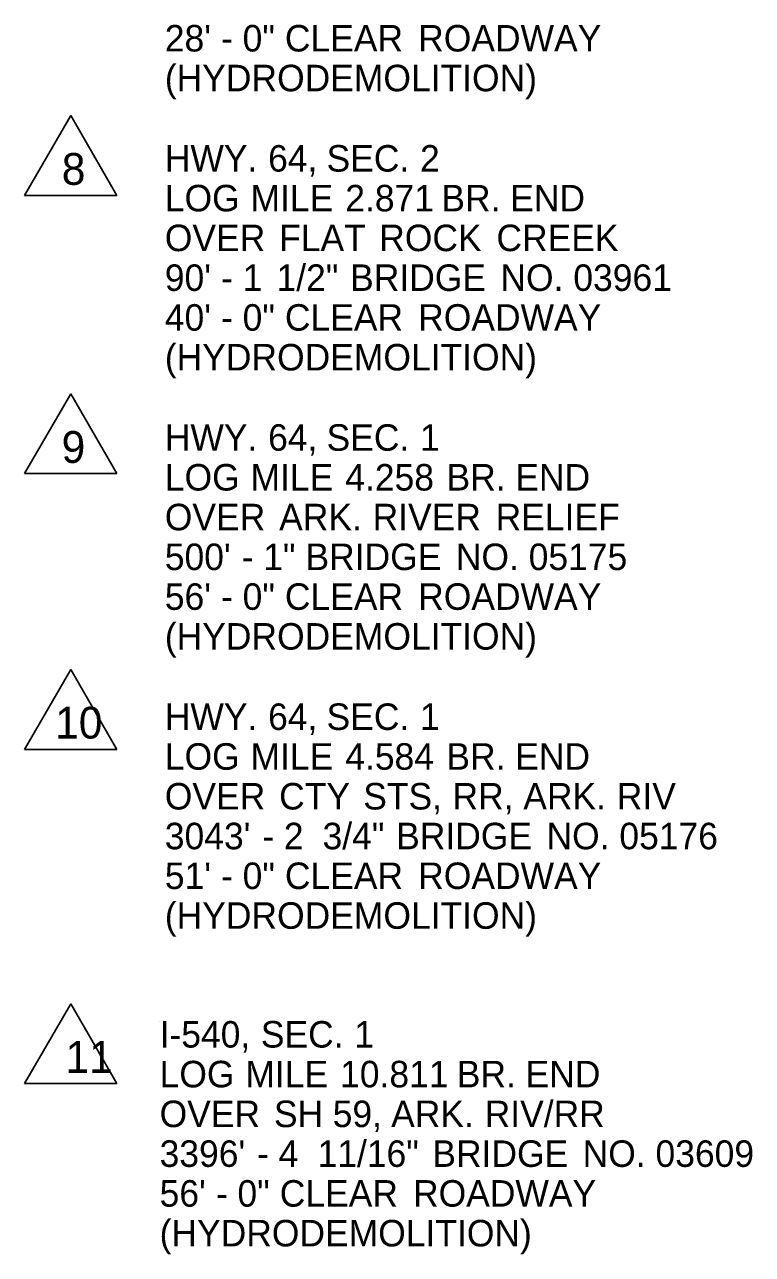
# Model space of a CAD drawing. Extents: x -17668 to 16999, y -17303 to 5867.
# Drawn here: x 1935 to 3994, y -2270 to 1209 of the extents above; entities that cross this region are included whole.
import ezdxf

# ---------------------------------------------------------------- set-up
doc = ezdxf.new("R2010")
doc.units = 0
doc.layers.add('48', color=7, linetype='Continuous')
doc.layers.add('Default', color=7, linetype='Continuous')

msp = doc.modelspace()

# ---------------------------------------------------------------- linework, layer by layer
at = {"layer": '48'}
for p, q in [((2065.7, 951.7), (1935.1, 725.5)), ((2196.3, 725.5), (2065.7, 951.7)), ((1935.1, 725.5), (2196.3, 725.5)), ((2065.7, 165.1), (1935.1, -61.1)), ((2196.3, -61.1), (2065.7, 165.1)), ((1935.1, -61.1), (2196.3, -61.1)), ((2065.7, -614.8), (1935.1, -841)), ((2196.3, -841), (2065.7, -614.8)), ((1935.1, -841), (2196.3, -841)), ((2065.7, -1560.5), (1935.1, -1786.7)), ((2196.3, -1786.7), (2065.7, -1560.5)), ((2317.1, -1609.7), (2317.1, -1609.7)), ((1935.1, -1786.7), (2196.3, -1786.7))]:
    msp.add_line(p, q, dxfattribs=at)

# ---------------------------------------------------------------- texts
for s, p in [('8', (2040.2, 755.9)), ('9', (2039.8, -30.7)), ('10', (2021.4, -810.6)), ('11', (2050.8, -1756.3))]:
    msp.add_text(s, height=90, dxfattribs=at).set_placement(p)
at = {"layer": 'Default'}
for s, p in [("28'", (2331.8, 1133.1)), (' 0"', (2524.1, 1133.1)), (' CLEAR', (2643.7, 1133.1)), (' ROADWAY', (3020.8, 1133.1)), (' -', (2463.4, 1133.1)), ('(HYDRODEMOLITION)', (2331.8, 1020.6)), ('HWY.', (2331.8, 793.3)), (' 64,', (2596.2, 793.3)), (' SEC.', (2761.6, 793.3)), (' 2', (3026.1, 793.3)), ('LOG', (2331.8, 680.8)), (' MILE', (2546.5, 680.8)), (' 2.871', (2814.5, 680.8)), (' BR.', (3086.4, 680.8)), (' END', (3281.1, 680.8)), ('OVER', (2331.8, 568.3)), (' FLAT', (2627.4, 568.3)), (' ROCK', (2910.6, 568.3)), (' CREEK', (3242.2, 568.3)), ("90'", (2331.8, 455.8)), (' 1', (2524.1, 455.8)), ('  1/2"', (2592.1, 455.8)), (' BRIDGE', (2828.2, 455.8)), (' NO.', (3253.5, 455.8)), (' 03961', (3459.8, 455.8)), (' -', (2463.4, 455.8)), ("40'", (2331.8, 343.3)), (' 0"', (2524.1, 343.3)), (' CLEAR', (2643.7, 343.3)), (' ROADWAY', (3020.8, 343.3)), (' -', (2463.4, 343.3)), ('(HYDRODEMOLITION)', (2331.8, 230.8)), ('HWY.', (2331.8, 3.6)), (' 64,', (2596.2, 3.6)), (' SEC.', (2761.6, 3.6)), (' 1', (3026.1, 3.6)), ('LOG', (2331.8, -108.9)), (' MILE', (2546.5, -108.9)), (' 4.258', (2814.5, -108.9)), (' BR.', (3101.1, -108.9)), (' END', (3295.7, -108.9)), ('OVER', (2331.8, -221.4)), (' ARK.', (2627.4, -221.4)), (' RIVER', (2891.9, -221.4)), (' RELIEF', (3239.9, -221.4)), ("500'", (2331.8, -333.9)), (' 1"', (2582.3, -333.9)), (' BRIDGE', (2702, -333.9)), (' NO.', (3127.3, -333.9)), (' 05175', (3333.5, -333.9)), (' -', (2521.6, -333.9)), ("56'", (2331.8, -446.4)), (' 0"', (2524.1, -446.4)), (' CLEAR', (2643.7, -446.4)), (' ROADWAY', (3020.8, -446.4)), (' -', (2463.4, -446.4)), ('(HYDRODEMOLITION)', (2331.8, -558.9)), ('HWY.', (2331.8, -786.2)), (' 64,', (2596.2, -786.2)), (' SEC.', (2761.6, -786.2)), (' 1', (3026.1, -786.2)), ('LOG', (2331.8, -898.7)), (' MILE', (2546.5, -898.7)), (' 4.584', (2814.5, -898.7)), (' BR.', (3100.6, -898.7)), (' END', (3295.3, -898.7)), ('OVER', (2331.8, -1011.2)), (' CTY', (2627.4, -1011.2)), (' STS,', (2865.3, -1011.2)), (' RR,', (3118, -1011.2)), (' ARK.', (3318.2, -1011.2)), (' RIV', (3582.8, -1011.2)), ("3043'", (2331.8, -1123.7)), (' 2', (2640.6, -1123.7)), ('  3/4"', (2722.4, -1123.7)), (' BRIDGE', (2958.5, -1123.7)), (' NO.', (3383.8, -1123.7)), (' 05176', (3590, -1123.7)), (' -', (2579.9, -1123.7)), ("51'", (2331.8, -1236.2)), (' 0"', (2524.1, -1236.2)), (' CLEAR', (2643.7, -1236.2)), (' ROADWAY', (3020.8, -1236.2)), (' -', (2463.4, -1236.2)), ('(HYDRODEMOLITION)', (2331.8, -1348.7)), ('I-540,', (2317.1, -1684.7)), (' SEC.', (2575.6, -1684.7)), (' 1', (2840.2, -1684.7)), ('LOG', (2317.1, -1797.2)), (' MILE', (2531.8, -1797.2)), (' 10.811', (2799.9, -1797.2)), (' BR.', (3130.1, -1797.2)), (' END', (3324.7, -1797.2)), ('OVER', (2317.1, -1909.7)), (' SH', (2612.7, -1909.7)), (' 59,', (2779, -1909.7)), (' ARK.', (2944.3, -1909.7)), (' RIV/RR', (3208.9, -1909.7)), ("3396'", (2317.1, -2022.2)), (' 4', (2625.9, -2022.2)), ('  11/16"', (2708.2, -2022.2)), (' BRIDGE', (3060.8, -2022.2)), (' NO.', (3486.1, -2022.2)), (' 03609', (3692.3, -2022.2)), (' -', (2565.2, -2022.2)), ("56'", (2317.1, -2134.7)), (' 0"', (2509.4, -2134.7)), (' CLEAR', (2629.1, -2134.7)), (' ROADWAY', (3006.2, -2134.7)), (' -', (2448.7, -2134.7)), ('(HYDRODEMOLITION)', (2317.1, -2247.2))]:
    msp.add_text(s, height=75, dxfattribs=at).set_placement(p)

doc.saveas('drawing.dxf')
